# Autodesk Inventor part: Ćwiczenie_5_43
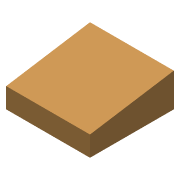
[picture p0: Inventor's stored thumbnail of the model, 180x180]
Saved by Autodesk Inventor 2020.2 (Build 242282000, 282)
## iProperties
Created: 2009-11
Part Number: Ćwiczenie_5_43
Document SubType Name: Modeling
Designer: F.Stasiak
Density: 1 g/cm^3
Material: Ogólny
Appearance: Pomarańczowy (blady)
Manager: www.cadconsulting.pl
Company: Fabian Stasiak CAD Consulting
Author: F.Stasiak
Subject: Zbiór ćwiczeń. Autodesk Inventor 2020. Kurs podstawowy
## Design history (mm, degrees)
sketch "Szkic2"
  geometry: L1 (250, 0)-(-250, 0); L2 (-250, 0)-(-250, 200); L3 (-250, 200)-(250, 120); L4 (250, 120)-(250, 0); 2 further points
  constraints: 8 end point, 2 perpendicular, 1 coincident, 1 horizontal, 1 midpoint
  dimensions: "d0" = 500 distance of L1.start L1.end; "d1" = 200 distance of L1.end L2.end; "d2" = 120 distance of L3.end L1.start
extrude "Wyciągnięcie proste1" new body sketch "Szkic2" stored distance "d3" = 500 (= d0); taper "d4" = 0 deg
node "Bryła1"
